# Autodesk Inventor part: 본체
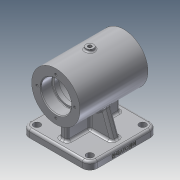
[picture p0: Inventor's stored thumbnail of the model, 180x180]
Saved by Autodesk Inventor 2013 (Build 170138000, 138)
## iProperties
Created: 2019-06
Part Number: 본체
Material: 알루미늄 6061
Document SubType Name: Modeling
Designer: a
Mass: 612.698 g
Surface Area: 622.653 cm^2
Volume: 226.088 cm^3
Density: 2.71 g/cm^3
Author: a
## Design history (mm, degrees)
sketch "스케치1"
  geometry: L1 (-45, 0)-(45, 0); L2 (-45, 0)-(-45, 32); L3 (-45, 32)-(45, 32); L4 (45, 32)-(45, 0); L5 (-45, 20)-(-30, 20); L6 (-30, 20)-(-30, 17); L7 (-30, 17)-(-24, 17); L8 (-24, 17)-(-24, 25); L9 (-24, 25)-(24, 25); L10 (24, 25)-(24, 17); L11 (24, 17)-(30, 17); L12 (30, 17)-(30, 20); L13 (30, 20)-(45, 20); 2 further points
  constraints: 26 end point, 7 parallel, 5 perpendicular, 2 point on line, 1 coincident, 1 horizontal, 1 midpoint
  dimensions: "d0" = 90 distance of L1.start L1.end; "d1" = 40 diameter of L5 L1; "d2" = 34 diameter of L7 L1; "d3" = 50 diameter of L9 L1; "d4" = 34 diameter of L11 L1; "d5" = 40 diameter of L13 L1; "d6" = 15 distance of L5.start L5.end; "d7" = 48 distance of L8.end L9.end; "d8" = 15 distance of L12.end L13.end; "d9" = 6 distance of L10.end L11.end; "d10" = 64 diameter of L3 L1
revolve "회전1" sketch "스케치1" stored, may be unused: angle "d11" = 90 deg
node "작업 평면1"
sketch "스케치2"
  geometry: L1 (45, 45)-(-45, 45); L2 (-45, 45)-(-45, -45); L3 (-45, -45)-(45, -45); L4 (45, -45)-(45, 45); L5 (45, 45)-(-45, -45); L6 (-45, 45)-(45, -45); 1 further point
  constraints: 12 end point, 2 midpoint, 2 parallel, 1 horizontal, 1 perpendicular
  dimensions: "d13" = 90 distance of L3.end L2.end; "d14" = 90 distance of L2.end L1.end
extrude "돌출1" join sketch "스케치2" distance "d15" = 10; taper "d16" = 0 deg
sketch "스케치3"
  geometry: L1 (-35, -5)-(35, -5); L2 (35, -5)-(35, 5); L3 (35, 5)-(-35, 5); L4 (-35, 5)-(-35, -5); L5 (-35, -5)-(35, 5); L6 (35, -5)-(-35, 5); 1 further point
  constraints: 12 end point, 2 midpoint, 2 parallel, 1 horizontal, 1 perpendicular
  dimensions: "d17" = 70 distance of L3.end L2.end; "d18" = 10 distance of L2.end L1.end
extrude "돌출2" join sketch "스케치3" stored distance "d19" = 10; taper "d20" = 0 deg
sketch "스케치4"
  geometry: L1 (-65, 45)-(-55, 45) reference; L2 (-55, 45)-(-55, 5) reference; L3 (-55, 5)-(-31.607, 5) reference; L4 (-31.607, -5)-(-55, -5) reference; L5 (-55, -5)-(-55, -45) reference; L6 (-55, -45)-(-65, -45) reference; L7 (-65, -45)-(-65, 45) reference; L8 (-22.189, 23.058)-(-55, 35); C1 r 25 at (0, 0) reference; A1 r 32 centre (0, 0) between (-31.607, -5) and (-31.607, 5) reference; 1 further point
  constraints: 2 end point, 1 point on circle, 1 point on line
  dimensions: "d21" = 10 distance from line of L8.end L1; "d22" = 20 deg angle of L1 L8
feature "리브1" sketch "스케치4" dims "d23" = 1, "d24" = 10, "d25" = 0, "d26" = 0, "d27" = 1, "d28" = 1
fillet "모깎기1" dims "d29" = 10
sketch "스케치5"
  geometry: A1 r 10 centre (35, 35) between (45, 35) and (35, 45) reference; A2 r 10 centre (-35, 35) between (-35, 45) and (-45, 35) reference; A3 r 10 centre (-35, -35) between (-45, -35) and (-35, -45) reference; A4 r 10 centre (35, -35) between (35, -45) and (45, -35) reference; 5 further points
  constraints: 4 coincident
hole "구멍1" sketch "스케치5" at (-35, 35), (35, 35), (35, -35), (-35, -35) diameter "d30" = 9; stored, may be unused: countersink angle "d34" = 90 deg, drill point angle "d36" = 118 deg; dims "d31" = 6, "d32" = 4, "d33" = 2, "d35" = 8
sketch "스케치6"
  geometry: L1 (-22, -40)-(22, -40); L2 (40, -22)-(40, 22); L3 (22, 40)-(-22, 40); L4 (-40, 22)-(-40, -22); L5 (-40, -40)-(40, 40); L6 (40, -40)-(-40, 40); L7 (-25, 35)-(-25, 37); L8 (25, 35)-(25, 37); L9 (-35, 25)-(-37, 25); L10 (-35, -25)-(-37, -25); L11 (-25, -35)-(-25, -37); L12 (25, -35)-(25, -37); L13 (35, -25)-(37, -25); L14 (35, 25)-(37, 25); A1 r 10 centre (35, -35) between (35, -45) and (45, -35) reference; A2 r 10 centre (35, 35) between (45, 35) and (35, 45) reference; A3 r 10 centre (-35, 35) between (-35, 45) and (-45, 35) reference; A4 r 10 centre (-35, -35) between (-45, -35) and (-35, -45) reference; A5 r 10 centre (-35, 35) between (-25, 35) and (-35, 25); A6 r 10 centre (-35, -35) between (-35, -25) and (-25, -35); A7 r 10 centre (35, -35) between (25, -35) and (35, -25); A8 r 10 centre (35, 35) between (25, 35) and (35, 25); A9 r 3 centre (-22, 37) between (-22, 40) and (-25, 37); A10 r 3 centre (22, 37) between (25, 37) and (22, 40); A11 r 3 centre (-37, 22) between (-37, 25) and (-40, 22); A12 r 3 centre (-37, -22) between (-40, -22) and (-37, -25); A13 r 3 centre (-22, -37) between (-25, -37) and (-22, -40); A14 r 3 centre (22, -37) between (22, -40) and (25, -37); A15 r 3 centre (37, -22) between (37, -25) and (40, -22); A16 r 3 centre (37, 22) between (40, 22) and (37, 25); 1 further point
  constraints: 28 end point, 24 point on circle, 24 tangent, 12 centre point, 9 perpendicular, 8 point on line, 4 coincident, 2 midpoint, 2 parallel, 1 horizontal
  dimensions: "d37" = 20 diameter of A5; "d38" = 20 diameter of A6; "d39" = 20 diameter of A7; "d40" = 20 diameter of A8; "d41" = 80 distance of L6.end L5.end; "d42" = 80 distance of L5.end L6.start; "d43" = 3 radius of A9; "d44" = 3 radius of A10; "d45" = 3 radius of A11; "d46" = 3 radius of A12; "d47" = 3 radius of A13; "d48" = 3 radius of A14; "d49" = 3 radius of A15; "d50" = 3 radius of A16
extrude "돌출3" cut sketch "스케치6" distance "d51" = 5; taper "d52" = 0 deg
node "작업 평면2"
sketch "스케치7"
  geometry: C1 r 5 at (0, 0); 1 further point
  constraints: 1 centre point, 1 coincident
  dimensions: "d54" = 10 diameter of C1
extrude "돌출4" join sketch "스케치7" stored distance "d55" = 5; taper "d56" = 0 deg
sketch "스케치8"
  geometry: C1 r 5 at (0, 0) reference; 1 further point
  constraints: 1 coincident
hole "구멍2" sketch "스케치8" at (0, 0) diameter "d57" = 4.917; stored, may be unused: countersink angle "d61" = 90 deg, drill point angle "d63" = 118 deg; dims "d58" = 6, "d59" = 4, "d60" = 2, "d62" = 8
fillet "모깎기2" dims "d64" = 2
chamfer "모따기1" distance "d65" = 1; stored, may be unused: second distance "d66" = 2, angle "d67" = 45 deg
fillet "모깎기3" dims "d68" = 0.6
fillet "모깎기4" dims "d69" = 3
fillet "모깎기5" dims "d70" = 3
fillet "모깎기6" dims "d71" = 3
fillet "모깎기7" dims "d72" = 3
sketch "스케치9"
  geometry: L1 (0, 0)-(0, 25); C1 r 21 at (0, 0) reference; 1 further point
  constraints: 2 end point, 1 coincident, 1 vertical
  dimensions: "d73" = 25 distance of L1.start L1.end
hole "구멍3" sketch "스케치9" at (0, 25) diameter "d74" = 3.242; stored, may be unused: countersink angle "d78" = 90 deg, drill point angle "d80" = 118 deg; dims "d75" = 7, "d76" = 4, "d77" = 2, "d79" = 9
sketch "스케치10"
  geometry: L1 (-10, 7)-(-10, 0) reference; L2 (0, 0)-(-10, 0) reference; 2 further points
  constraints: 1 other
  dimensions: "d84" = 45 distance from line of point (35, 4) L1; "d85" = 4 distance from line of point (35, 4) L2
feature "엠보싱1" sketch "스케치10" dims "d0" = 90, "d1" = 40, "d2" = 34, "d3" = 50, "d4" = 34, "d5" = 40, "d6" = 15, "d7" = 48, "d8" = 15, "d9" = 6, "d10" = 64, "d13" = 90, "d14" = 90, "d86" = 0.5, "d87" = 0
node "솔리드1"
mirror "대칭1"
pattern_circular "원형 패턴1" dims angle "d82" = 360 deg
mirror "대칭2"
node "절단 모서리 투영1"
other parameters: "d12" = -65, "d53" = 35
